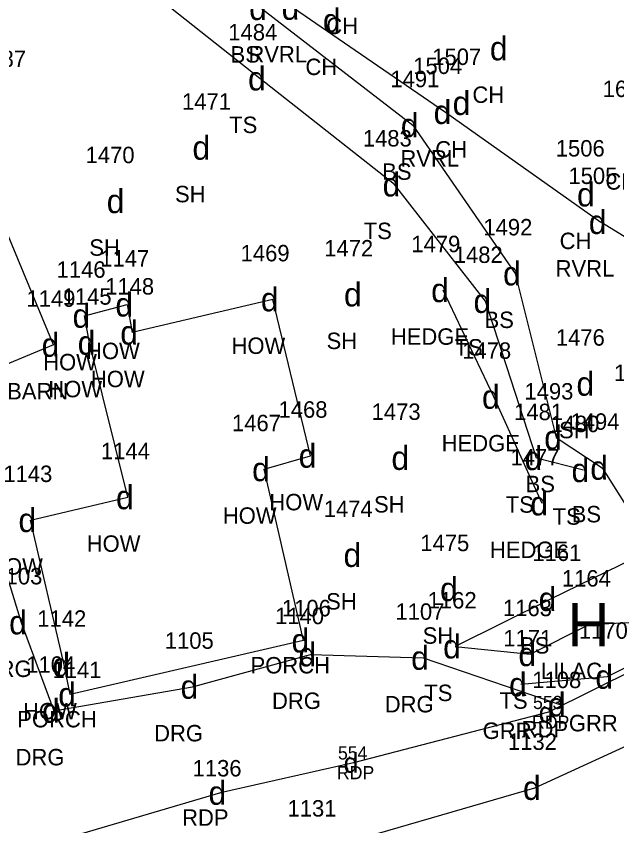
# Model space of a CAD drawing. Extents: x 461160 to 461373, y 202903 to 203086.
# Drawn here: x 461256.86 to 461284.61, y 202948.72 to 202986.14 of the extents above; entities that cross this region are included whole.
import ezdxf

# ---------------------------------------------------------------- set-up
doc = ezdxf.new("R2010")
doc.units = 0
for name, color, linetype in [('Level 11', 7, 'Continuous'), ('Level 12', 7, 'Continuous'), ('Level 13', 7, 'Continuous'), ('Level 14', 7, 'Continuous'), ('Level 17', 7, 'Continuous'), ('Level 46', 7, 'Continuous'), ('Level 47', 7, 'Continuous'), ('Level 48', 7, 'Continuous'), ('Level 49', 7, 'Continuous')]:
    doc.layers.add(name, color=color, linetype=linetype)

msp = doc.modelspace()

# ---------------------------------------------------------------- linework, layer by layer
at = {"layer": 'Level 11'}
msp.add_line((461289.972, 202958.214), (461281.455, 202953.963), dxfattribs=at)
for points in [[(461225.839, 202955.41), (461233.005, 202955.24), (461234.746, 202949.819), (461236.741, 202943.832), (461244.347, 202945.91), (461249.598, 202947.658), (461248.538, 202952.244), (461248.364, 202955.436), (461251.269, 202957.848), (461253.374, 202957.829), (461254.869, 202953.096), (461255.375, 202954.845), (461254.153, 202958.959), (461250.057, 202966.484), (461253.635, 202968.084), (461255.533, 202963.152), (461257.085, 202958.116), (461258.603, 202954.031), (461265.002, 202955.14), (461270.449, 202956.639), (461275.656, 202956.479), (461281.979, 202954.324)], [(461281.455, 202953.963), (461272.444, 202951.631), (461266.295, 202950.239)], [(461266.295, 202950.239), (461255.843, 202947.153), (461244.186, 202944.178), (461233.496, 202941.961), (461227.074, 202940.327)]]:
    msp.add_lwpolyline(points, dxfattribs=at)
at = {"layer": 'Level 12'}
msp.add_lwpolyline([(461294.92, 202961.79), (461290.984, 202959.008), (461284.162, 202955.604), (461280.179, 202955.252)], dxfattribs=at)
at = {"layer": 'Level 13'}
for points in [[(461258.585, 202970.946), (461255.803, 202977.642), (461252.296, 202976.227), (461250.862, 202979.915), (461245.048, 202977.524), (461246.533, 202974.042)], [(461258.585, 202970.946), (461244.676, 202965.151), (461241.951, 202972.027), (461246.533, 202974.042)], [(461270.13, 202957.279), (461268.31, 202965.197), (461270.46, 202965.82), (461268.713, 202973.048), (461262.218, 202971.512)], [(461270.13, 202957.279), (461259.354, 202954.787), (461259.083, 202956.156), (461257.515, 202962.848), (461262.023, 202963.902), (461260.251, 202971.045), (461260.013, 202972.29), (461261.993, 202972.808), (461262.218, 202971.512)]]:
    msp.add_lwpolyline(points, dxfattribs=at)
at = {"layer": 'Level 14'}
msp.add_lwpolyline([(461281.16, 202963.615), (461278.929, 202968.542), (461276.58, 202973.472)], dxfattribs=at)
at = {"layer": 'Level 17'}
for points in [[(461263.48, 202991.79), (461269.671, 202986.522), (461276.694, 202981.707), (461283.863, 202976.623)], [(461329.105, 202940.329), (461320.674, 202945.977), (461310.964, 202954.304), (461302.434, 202959.989), (461295.777, 202967.953), (461287.62, 202974.31), (461283.863, 202976.623)]]:
    msp.add_lwpolyline(points, dxfattribs=at)
at = {"layer": 'Level 48'}
for points in [[(461262.397, 202991.157), (461268.172, 202986.514), (461275.177, 202981.097), (461279.904, 202974.246), (461281.802, 202966.659), (461283.93, 202965.263), (461286.001, 202961.968), (461287.188, 202964.973), (461289.154, 202965.814)], [(461262.397, 202991.157), (461268.172, 202986.514), (461275.177, 202981.097), (461279.904, 202974.246), (461281.802, 202966.659), (461283.93, 202965.263), (461286.001, 202961.968), (461287.188, 202964.973), (461289.154, 202965.814)], [(461283.063, 202965.154), (461280.895, 202965.708), (461278.537, 202972.974), (461274.336, 202978.356), (461268.122, 202983.257), (461260.239, 202989.507)], [(461283.063, 202965.154), (461280.895, 202965.708), (461278.537, 202972.974), (461274.336, 202978.356), (461268.122, 202983.257), (461260.239, 202989.507)], [(461294.096, 202964.725), (461290.058, 202963.299), (461286.054, 202961.4), (461281.542, 202959.198), (461277.133, 202957.003), (461280.61, 202956.648), (461283.332, 202958.017), (461286.382, 202958.177), (461290.659, 202959.565)], [(461294.096, 202964.725), (461290.058, 202963.299), (461286.054, 202961.4), (461281.542, 202959.198), (461277.133, 202957.003), (461280.61, 202956.648), (461283.332, 202958.017), (461286.382, 202958.177), (461290.659, 202959.565)], [(461211.555, 202934.121), (461222.234, 202936.16), (461232.093, 202938.078), (461241.693, 202939.978), (461251.734, 202942.643), (461261.209, 202945.054), (461270.211, 202947.385), (461280.824, 202950.466), (461289.045, 202954.252), (461296.764, 202959.518)]]:
    msp.add_lwpolyline(points, dxfattribs=at)

# ---------------------------------------------------------------- texts
at = {"layer": 'Level 14'}
msp.add_text('H', height=2, dxfattribs=at).set_placement((461282.332, 202957.017))
at = {"layer": 'Level 46'}
for s, height, p in [(' CH  ', 0.76, (461270.902, 202985.315)), (' BS  ', 0.76, (461266.482, 202983.994)), (' RVRL  ', 0.76, (461267.305, 202984.002)), (' CH  ', 0.76, (461269.941, 202983.418)), (' CH  ', 0.76, (461277.656, 202982.131)), (' TS  ', 0.76, (461266.42, 202980.737)), (' CH  ', 0.76, (461275.937, 202979.604)), (' RVRL  ', 0.76, (461274.328, 202979.187)), (' BS  ', 0.76, (461273.487, 202978.577)), (' CH  ', 0.76, (461283.797, 202978.122)), (' SH  ', 0.76, (461263.916, 202977.537)), (' TS  ', 0.76, (461272.634, 202975.836)), (' CH  ', 0.76, (461281.682, 202975.374)), (' SH  ', 0.76, (461259.957, 202975.066)), (' RVRL  ', 0.76, (461281.497, 202974.103)), (' BS  ', 0.76, (461278.214, 202971.726)), (' SH  ', 0.76, (461270.917, 202970.753)), (' HEDGE  ', 0.76, (461273.885, 202970.952)), (' HOW  ', 0.76, (461266.526, 202970.528)), (' TS  ', 0.76, (461276.835, 202970.454)), (' HOW  ', 0.76, (461259.806, 202970.288)), (' HOW  ', 0.76, (461257.826, 202969.77)), (' HOW  ', 0.76, (461260.031, 202968.992)), (' HOW  ', 0.76, (461258.064, 202968.525)), (' BARN  ', 0.76, (461256.162, 202968.426)), (' SH  ', 0.76, (461281.656, 202966.63)), (' HEDGE  ', 0.76, (461276.234, 202966.022)), (' BS  ', 0.76, (461280.112, 202964.139)), (' HOW  ', 0.76, (461268.273, 202963.3)), (' SH  ', 0.76, (461273.108, 202963.199)), (' TS  ', 0.76, (461279.193, 202963.188)), (' HOW  ', 0.76, (461266.123, 202962.677)), (' TS  ', 0.76, (461281.361, 202962.634)), (' BS  ', 0.76, (461282.24, 202962.743)), (' HOW  ', 0.76, (461259.836, 202961.382)), (' HEDGE  ', 0.76, (461278.465, 202961.095)), (' HOW  ', 0.76, (461255.328, 202960.328)), (' SH  ', 0.76, (461270.896, 202958.713)), (' SH  ', 0.76, (461275.356, 202957.133)), (' BS  ', 0.76, (461279.852, 202956.678)), (' DRG  ', 0.76, (461255.033, 202955.596)), (' PORCH  ', 0.76, (461267.405, 202955.759)), (' LILAC  ', 0.76, (461280.819, 202955.497)), (' TS  ', 0.76, (461275.431, 202954.483)), (' DRG  ', 0.76, (461268.397, 202954.119)), (' DRG  ', 0.76, (461273.604, 202953.959)), (' TS  ', 0.76, (461278.908, 202954.128)), ('553', 0.609, (461280.736, 202954.115)), (' HOW  ', 0.76, (461256.896, 202953.636)), (' PORCH  ', 0.76, (461256.629, 202953.267)), (' RDP  ', 0.76, (461279.927, 202952.804)), ('RDP', 0.609, (461280.691, 202953.202)), (' GRR  ', 0.76, (461282.11, 202953.084)), (' DRG  ', 0.76, (461262.95, 202952.62)), (' GRR  ', 0.76, (461278.127, 202952.732)), (' DRG  ', 0.76, (461256.551, 202951.511)), ('554', 0.609, (461271.725, 202951.783)), ('RDP', 0.609, (461271.68, 202950.87)), (' RDP  ', 0.76, (461264.243, 202948.719))]:
    msp.add_text(s, height=height, dxfattribs=at).set_placement(p)
at = {"layer": 'Level 47'}
for height, p in [(1.1, (461267.622, 202985.964)), (1.1, (461269.121, 202985.972)), (1.1, (461271.027, 202985.388)), (1.1, (461278.742, 202984.101)), (1.1, (461267.572, 202982.707)), (1.1, (461277.023, 202981.574)), (1.1, (461276.144, 202981.157)), (1.1, (461274.627, 202980.547)), (1.1, (461265.002, 202979.507)), (1.1, (461273.786, 202977.806)), (1.1, (461282.768, 202977.344)), (1.1, (461261.043, 202977.036)), (1.1, (461283.313, 202976.073)), (1.1, (461279.354, 202973.696)), (1.1, (461272.003, 202972.723)), (1.1, (461276.03, 202972.922)), (1.1, (461261.443, 202972.258)), (1.1, (461268.163, 202972.498)), (1.1, (461277.987, 202972.424)), (1.1, (461259.463, 202971.74)), (1.1, (461261.668, 202970.962)), (1.1, (461258.035, 202970.396)), (1.1, (461259.701, 202970.495)), (1.1, (461282.742, 202968.6)), (1.1, (461278.379, 202967.992)), (1.1, (461281.252, 202966.109)), (1.1, (461269.91, 202965.27)), (1.1, (461274.194, 202965.169)), (1.1, (461280.345, 202965.158)), (1.1, (461267.76, 202964.647)), (1.1, (461282.513, 202964.604)), (1.1, (461283.38, 202964.713)), (1.1, (461261.473, 202963.352)), (1.1, (461280.61, 202963.065)), (1.1, (461256.965, 202962.298)), (1.1, (461271.982, 202960.683)), (1.1, (461276.442, 202959.103)), (1.1, (461280.992, 202958.648)), (1.1, (461256.535, 202957.566)), (1.1, (461269.58, 202956.729)), (1.1, (461276.583, 202956.453)), (1.1, (461269.899, 202956.089)), (1.1, (461275.106, 202955.929)), (1.1, (461280.06, 202956.098)), (1.1, (461258.533, 202955.606)), (1.1, (461283.612, 202955.054)), (1.1, (461279.629, 202954.702)), (1.1, (461264.452, 202954.59)), (1.1, (461258.804, 202954.237)), (1.1, (461281.429, 202953.774)), (1.1, (461258.053, 202953.481)), (0.914, (461280.998, 202953.506)), (0.914, (461271.987, 202951.174)), (1.1, (461280.274, 202949.916)), (1.1, (461265.745, 202949.689))]:
    msp.add_text('d', height=height, dxfattribs=at).set_placement(p)
at = {"layer": 'Level 49'}
for s, p in [(' 1484 ', (461266.378, 202985.017)), (' 1507 ', (461275.799, 202983.884)), (' 1487 ', (461254.773, 202983.789)), (' 1504 ', (461274.92, 202983.467)), (' 1491 ', (461273.864, 202982.857)), (' 1682 ', (461283.671, 202982.402)), (' 1471 ', (461264.239, 202981.817)), (' 1483 ', (461272.592, 202980.116)), (' 1470 ', (461259.786, 202979.346)), (' 1506 ', (461281.505, 202979.654)), (' 1505 ', (461282.089, 202978.383)), (' 1492 ', (461278.16, 202976.006)), (' 1479 ', (461274.833, 202975.232)), (' 1472 ', (461270.809, 202975.033)), (' 1147 ', (461260.465, 202974.568)), (' 1469 ', (461266.948, 202974.808)), (' 1482 ', (461276.793, 202974.734)), (' 1146 ', (461258.446, 202974.05)), (' 1148 ', (461260.69, 202973.272)), (' 1149 ', (461257.054, 202972.706)), (' 1145 ', (461258.723, 202972.805)), (' 1476 ', (461281.509, 202970.91)), (' 1478 ', (461277.185, 202970.302)), (' 1500 ', (461284.196, 202969.276)), (' 1493 ', (461280.058, 202968.419)), (' 1468 ', (461268.698, 202967.58)), (' 1473 ', (461273, 202967.479)), (' 1481 ', (461279.582, 202967.468)), (' 1494 ', (461282.186, 202967.023)), (' 1467 ', (461266.548, 202966.957)), (' 1480 ', (461281.256, 202966.914)), (' 1144 ', (461260.495, 202965.662)), (' 1477 ', (461279.416, 202965.375)), (' 1143 ', (461255.987, 202964.608)), (' 1474 ', (461270.788, 202962.993)), (' 1475 ', (461275.248, 202961.413)), (' 1161 ', (461280.426, 202960.958)), (' 1103 ', (461255.527, 202959.876)), (' 1164 ', (461281.786, 202959.777)), (' 1162 ', (461275.587, 202958.763)), (' 1106 ', (461268.852, 202958.399)), (' 1163 ', (461279.064, 202958.408)), (' 1140 ', (461268.539, 202958.039)), (' 1107 ', (461274.098, 202958.239)), (' 1142 ', (461257.555, 202957.916)), (' 1170 ', (461282.571, 202957.364)), (' 1105 ', (461263.444, 202956.9)), (' 1171 ', (461279.081, 202957.012)), (' 1104 ', (461257.045, 202955.791)), (' 1141 ', (461258.256, 202955.547)), (' 1108 ', (461280.421, 202955.084)), (' 1132 ', (461279.296, 202952.226)), (' 1136 ', (461264.728, 202950.999)), (' 1131 ', (461269.113, 202949.145))]:
    msp.add_text(s, height=0.76, dxfattribs=at).set_placement(p)

doc.saveas('drawing.dxf')
